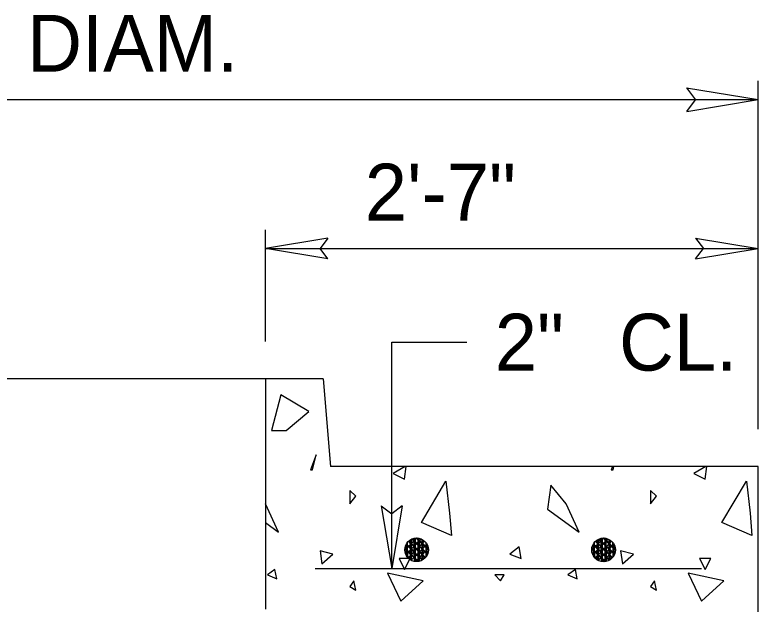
# Model space of a CAD drawing. Extents: x 1.8 to 9.1, y -6 to 4.
# Drawn here: x 5.989 to 6.774, y 1.281 to 1.904 of the extents above; entities that cross this region are included whole.
import ezdxf

# ---------------------------------------------------------------- set-up
doc = ezdxf.new("R2010")
doc.units = 0
for name, color, linetype in [('DETL-DIMS', 7, 'Continuous'), ('DETL-LINE', 7, 'Continuous'), ('DETL-NOTE', 7, 'Continuous'), ('DETL-PATT', 7, 'Continuous')]:
    doc.layers.add(name, color=color, linetype=linetype)

msp = doc.modelspace()

# ---------------------------------------------------------------- linework, layer by layer
at = {"layer": 'DETL-DIMS'}
for p, q in [((6.77389, 1.4659), (6.77389, 1.83373)), ((6.69839, 1.82649), (6.77389, 1.81407)), ((6.69839, 1.82649), (6.70786, 1.81395)), ((5.11586, 1.81407), (6.77389, 1.81407)), ((6.69846, 1.80134), (6.77389, 1.81407)), ((6.69846, 1.80134), (6.70786, 1.81395)), ((6.25356, 1.55859), (6.25356, 1.6765)), ((6.3196, 1.66786), (6.25356, 1.65685)), ((6.3196, 1.66786), (6.31134, 1.65685)), ((6.70786, 1.66786), (6.77389, 1.65685)), ((6.70786, 1.66786), (6.71611, 1.65685)), ((6.3196, 1.64584), (6.25356, 1.65685)), ((6.25356, 1.65685), (6.77389, 1.65685)), ((6.3196, 1.64584), (6.31134, 1.65685)), ((6.70786, 1.64584), (6.77389, 1.65685)), ((6.70786, 1.64584), (6.71611, 1.65685)), ((6.38689, 1.31894), (6.38689, 1.55788)), ((6.38689, 1.55788), (6.46629, 1.55788)), ((6.37588, 1.38497), (6.38689, 1.31894)), ((6.37588, 1.38497), (6.38689, 1.37672)), ((6.39789, 1.38497), (6.38689, 1.31894)), ((6.39789, 1.38497), (6.38689, 1.37672))]:
    msp.add_line(p, q, dxfattribs=at)
at = {"layer": 'DETL-LINE'}
for p, q in [((6.31468, 1.51928), (5.26346, 1.51928)), ((6.25356, 1.51928), (6.25356, 1.27578)), ((6.31468, 1.51928), (6.32239, 1.4266)), ((6.77389, 1.4266), (6.32239, 1.4266)), ((6.77389, 1.189), (6.77389, 1.4266)), ((6.41169, 1.3494), (6.40238, 1.34001)), ((6.41169, 1.34358), (6.40241, 1.33415)), ((6.40379, 1.33061), (6.40371, 1.34386)), ((6.41311, 1.33336), (6.40371, 1.34268)), ((6.41342, 1.3338), (6.40403, 1.34311)), ((6.4146, 1.34649), (6.40528, 1.3371)), ((6.4067, 1.33478), (6.40662, 1.34803)), ((6.41601, 1.33631), (6.40662, 1.34559)), ((6.40674, 1.33065), (6.40666, 1.3439)), ((6.41633, 1.33675), (6.4069, 1.34606)), ((6.40788, 1.33478), (6.4078, 1.34803)), ((6.40792, 1.33065), (6.40784, 1.3439)), ((6.41751, 1.34944), (6.40819, 1.34005)), ((6.41755, 1.34362), (6.40823, 1.33419)), ((6.41892, 1.33926), (6.40953, 1.34854)), ((6.41896, 1.3334), (6.40957, 1.34272)), ((6.41924, 1.33969), (6.4098, 1.34901)), ((6.41928, 1.33384), (6.4098, 1.34315)), ((6.41083, 1.33478), (6.41075, 1.34803)), ((6.41087, 1.33065), (6.41079, 1.3439)), ((6.42042, 1.34653), (6.41114, 1.33714)), ((6.41201, 1.33482), (6.41193, 1.34803)), ((6.41204, 1.33069), (6.41197, 1.3439)), ((6.42187, 1.33635), (6.41244, 1.34563)), ((6.42219, 1.33678), (6.41271, 1.3461)), ((6.42336, 1.34362), (6.41409, 1.33423)), ((6.41495, 1.33482), (6.41487, 1.34807)), ((6.41499, 1.33069), (6.41491, 1.34394)), ((6.42478, 1.3393), (6.41535, 1.34858)), ((6.42505, 1.33973), (6.41562, 1.34901)), ((6.41613, 1.33482), (6.41605, 1.34807)), ((6.41617, 1.33069), (6.41609, 1.34394)), ((6.41908, 1.33486), (6.419, 1.34807)), ((6.41912, 1.33073), (6.41904, 1.34398)), ((6.42026, 1.33486), (6.42018, 1.3481)), ((6.4203, 1.33073), (6.42022, 1.34398)), ((6.60916, 1.34932), (6.59985, 1.33993)), ((6.60916, 1.34351), (6.59989, 1.33407)), ((6.60126, 1.33053), (6.60118, 1.34378)), ((6.61058, 1.33329), (6.60118, 1.3426)), ((6.61089, 1.33372), (6.6015, 1.34303)), ((6.61207, 1.34641), (6.60276, 1.33702)), ((6.60417, 1.3347), (6.60409, 1.34795)), ((6.61349, 1.33623), (6.60409, 1.34551)), ((6.60421, 1.33057), (6.60413, 1.34382)), ((6.6138, 1.33667), (6.60437, 1.34598)), ((6.60535, 1.3347), (6.60527, 1.34795)), ((6.60539, 1.33057), (6.60531, 1.34382)), ((6.61498, 1.34936), (6.60566, 1.33997)), ((6.61502, 1.34354), (6.6057, 1.33411)), ((6.61639, 1.33918), (6.607, 1.34846)), ((6.61643, 1.33333), (6.60704, 1.34264)), ((6.61671, 1.33961), (6.60728, 1.34893)), ((6.61675, 1.33376), (6.60728, 1.34307)), ((6.6083, 1.3347), (6.60822, 1.34795)), ((6.60834, 1.33057), (6.60826, 1.34382)), ((6.61789, 1.34645), (6.60861, 1.33706)), ((6.60948, 1.33474), (6.6094, 1.34795)), ((6.60952, 1.33061), (6.60944, 1.34382)), ((6.61934, 1.33627), (6.60991, 1.34555)), ((6.61966, 1.33671), (6.61018, 1.34602)), ((6.62084, 1.34354), (6.61156, 1.33415)), ((6.61242, 1.33474), (6.61235, 1.34799)), ((6.61246, 1.33061), (6.61239, 1.34386)), ((6.62225, 1.33922), (6.61282, 1.3485)), ((6.62253, 1.33965), (6.61309, 1.34893)), ((6.6136, 1.33474), (6.61353, 1.34799)), ((6.61364, 1.33061), (6.61356, 1.34386)), ((6.61655, 1.33478), (6.61647, 1.34799)), ((6.61659, 1.33065), (6.61651, 1.3439)), ((6.61773, 1.33478), (6.61765, 1.34803)), ((6.61777, 1.33065), (6.61769, 1.3439)), ((6.41024, 1.33046), (6.4008, 1.33977)), ((6.41051, 1.33089), (6.40112, 1.34016)), ((6.41315, 1.32755), (6.40375, 1.33686)), ((6.41346, 1.32798), (6.40407, 1.3373)), ((6.41464, 1.34071), (6.40532, 1.33124)), ((6.41605, 1.3305), (6.40666, 1.33977)), ((6.41637, 1.33093), (6.40694, 1.3402)), ((6.41759, 1.33781), (6.40827, 1.32833)), ((6.419, 1.32759), (6.40957, 1.3369)), ((6.41932, 1.32802), (6.40984, 1.33733)), ((6.4109, 1.32653), (6.41079, 1.33977)), ((6.42046, 1.34071), (6.41118, 1.33128)), ((6.41204, 1.32656), (6.41197, 1.33977)), ((6.42191, 1.33053), (6.41248, 1.33981)), ((6.42222, 1.33093), (6.41275, 1.34024)), ((6.4234, 1.33785), (6.41409, 1.32837)), ((6.41499, 1.32656), (6.41491, 1.33981)), ((6.41617, 1.32656), (6.41609, 1.33981)), ((6.60771, 1.33038), (6.59827, 1.33969)), ((6.60798, 1.33081), (6.59859, 1.34009)), ((6.61062, 1.32747), (6.60122, 1.33678)), ((6.61093, 1.3279), (6.60154, 1.33722)), ((6.61211, 1.34064), (6.6028, 1.33116)), ((6.61353, 1.33042), (6.60413, 1.33969)), ((6.61384, 1.33085), (6.60441, 1.34013)), ((6.61506, 1.33773), (6.60574, 1.32826)), ((6.61647, 1.32751), (6.60704, 1.33682)), ((6.61679, 1.32794), (6.60732, 1.33726)), ((6.60838, 1.32645), (6.60826, 1.33969)), ((6.61793, 1.34064), (6.60865, 1.3312)), ((6.60952, 1.32649), (6.60944, 1.33969)), ((6.61938, 1.33046), (6.60995, 1.33973)), ((6.6197, 1.33085), (6.61022, 1.34016)), ((6.62088, 1.33777), (6.61156, 1.32829)), ((6.61246, 1.32649), (6.61239, 1.33973)), ((6.61364, 1.32649), (6.61356, 1.33973)), ((6.30592, 1.31894), (6.71399, 1.31894))]:
    msp.add_line(p, q, dxfattribs=at)
for points in [[(6.41326, 1.35105), (6.40524, 1.34296)], [(6.41326, 1.35105), (6.40815, 1.3459)], [(6.41629, 1.3426), (6.40863, 1.35019)], [(6.41334, 1.34551), (6.40863, 1.35019)], [(6.41039, 1.34838), (6.40863, 1.35019)], [(6.41083, 1.33891), (6.41075, 1.35082)], [(6.41079, 1.34303), (6.41075, 1.35082)], [(6.41075, 1.34716), (6.41075, 1.35082)], [(6.41197, 1.33895), (6.41189, 1.35101)], [(6.41197, 1.34307), (6.41189, 1.35101)], [(6.41193, 1.3472), (6.41189, 1.35101)], [(6.42183, 1.34217), (6.41287, 1.35105)], [(6.41888, 1.34508), (6.41287, 1.35105)], [(6.41594, 1.34799), (6.41287, 1.35105)], [(6.41299, 1.3509), (6.41287, 1.35105)], [(6.42215, 1.34264), (6.41358, 1.35105)], [(6.4192, 1.34555), (6.41358, 1.35105)], [(6.41625, 1.34842), (6.41358, 1.35105)], [(6.41495, 1.33895), (6.41487, 1.3509)], [(6.41491, 1.34307), (6.41487, 1.3509)], [(6.41487, 1.3472), (6.41487, 1.3509)], [(6.41609, 1.33895), (6.41601, 1.3507)], [(6.41609, 1.34307), (6.41601, 1.3507)], [(6.41605, 1.3472), (6.41601, 1.3507)], [(6.61073, 1.35097), (6.60272, 1.34288)], [(6.61073, 1.35097), (6.60563, 1.34582)], [(6.6083, 1.33883), (6.60822, 1.35074)], [(6.60826, 1.34296), (6.60822, 1.35074)], [(6.60822, 1.34708), (6.60822, 1.35074)], [(6.60944, 1.33887), (6.60936, 1.35093)], [(6.60944, 1.34299), (6.60936, 1.35093)], [(6.6094, 1.34712), (6.60936, 1.35093)], [(6.6193, 1.34209), (6.61034, 1.35097)], [(6.61636, 1.345), (6.61034, 1.35097)], [(6.61341, 1.34791), (6.61034, 1.35097)], [(6.61046, 1.35082), (6.61034, 1.35097)], [(6.61962, 1.34256), (6.61105, 1.35097)], [(6.61667, 1.34547), (6.61105, 1.35097)], [(6.61372, 1.34834), (6.61105, 1.35097)], [(6.61242, 1.33887), (6.61235, 1.35082)], [(6.61239, 1.34299), (6.61235, 1.35082)], [(6.61235, 1.34712), (6.61235, 1.35082)], [(6.61356, 1.33887), (6.61349, 1.35062)], [(6.61356, 1.34299), (6.61349, 1.35062)], [(6.61353, 1.34712), (6.61349, 1.35062)], [(6.40878, 1.34649), (6.40072, 1.33836)], [(6.40587, 1.34354), (6.40072, 1.33836)], [(6.4102, 1.33627), (6.4021, 1.34425)], [(6.40725, 1.33918), (6.4021, 1.34425)], [(6.40434, 1.34209), (6.4021, 1.34425)], [(6.41047, 1.33671), (6.40234, 1.34476)], [(6.40752, 1.33961), (6.40234, 1.34476)], [(6.40462, 1.34252), (6.40234, 1.34476)], [(6.40257, 1.33474), (6.40253, 1.34504)], [(6.40257, 1.33887), (6.40253, 1.34504)], [(6.40253, 1.34299), (6.40253, 1.34504)], [(6.40261, 1.33203), (6.40253, 1.34386)], [(6.40375, 1.33474), (6.40367, 1.34665)], [(6.40371, 1.33887), (6.40367, 1.34665)], [(6.40371, 1.34299), (6.40367, 1.34665)], [(6.41307, 1.33922), (6.40458, 1.34763)], [(6.41016, 1.34213), (6.40458, 1.34763)], [(6.40725, 1.34504), (6.40458, 1.34763)], [(6.41338, 1.33965), (6.40497, 1.34795)], [(6.41043, 1.34256), (6.40497, 1.34795)], [(6.40749, 1.34547), (6.40497, 1.34795)], [(6.4067, 1.33891), (6.40662, 1.34917)], [(6.40666, 1.34303), (6.40662, 1.34917)], [(6.40662, 1.34716), (6.40662, 1.34917)], [(6.40784, 1.33891), (6.4078, 1.34983)], [(6.40784, 1.34303), (6.4078, 1.34983)], [(6.4078, 1.34716), (6.4078, 1.34983)], [(6.41598, 1.34217), (6.40811, 1.34995)], [(6.41303, 1.34504), (6.40811, 1.34995)], [(6.41012, 1.34795), (6.40811, 1.34995)], [(6.4181, 1.35003), (6.4111, 1.34299)], [(6.42164, 1.34775), (6.41405, 1.34009)], [(6.42462, 1.3336), (6.41539, 1.34276)], [(6.42482, 1.33415), (6.41566, 1.34319)], [(6.42419, 1.34449), (6.41696, 1.33718)], [(6.42564, 1.33844), (6.41826, 1.34567)], [(6.42564, 1.33914), (6.41857, 1.34614)], [(6.41908, 1.33899), (6.419, 1.3496)], [(6.41904, 1.34311), (6.419, 1.3496)], [(6.419, 1.34724), (6.419, 1.3496)], [(6.42022, 1.33899), (6.42018, 1.34893)], [(6.42022, 1.34311), (6.42018, 1.34893)], [(6.42018, 1.34724), (6.42018, 1.34893)], [(6.42564, 1.33844), (6.4212, 1.3428)], [(6.42564, 1.33914), (6.42152, 1.34323)], [(6.42321, 1.33486), (6.42313, 1.3461)], [(6.42321, 1.33899), (6.42313, 1.3461)], [(6.42317, 1.34311), (6.42313, 1.3461)], [(6.42325, 1.33124), (6.42317, 1.34398)], [(6.42439, 1.3349), (6.42431, 1.34421)], [(6.42435, 1.33899), (6.42431, 1.34421)], [(6.42435, 1.34311), (6.42431, 1.34421)], [(6.42439, 1.33309), (6.42431, 1.34398)], [(6.60625, 1.34641), (6.5982, 1.33828)], [(6.60335, 1.34347), (6.5982, 1.33828)], [(6.60767, 1.33619), (6.59957, 1.34417)], [(6.60472, 1.3391), (6.59957, 1.34417)], [(6.60181, 1.34201), (6.59957, 1.34417)], [(6.60794, 1.33663), (6.59981, 1.34468)], [(6.605, 1.33954), (6.59981, 1.34468)], [(6.60209, 1.34244), (6.59981, 1.34468)], [(6.60004, 1.33466), (6.6, 1.34496)], [(6.60004, 1.33879), (6.6, 1.34496)], [(6.6, 1.34292), (6.6, 1.34496)], [(6.60008, 1.33195), (6.6, 1.34378)], [(6.60122, 1.33466), (6.60114, 1.34657)], [(6.60118, 1.33879), (6.60114, 1.34657)], [(6.60118, 1.34292), (6.60114, 1.34657)], [(6.61054, 1.33914), (6.60205, 1.34755)], [(6.60763, 1.34205), (6.60205, 1.34755)], [(6.60472, 1.34496), (6.60205, 1.34755)], [(6.61085, 1.33958), (6.60244, 1.34787)], [(6.6079, 1.34248), (6.60244, 1.34787)], [(6.60496, 1.34539), (6.60244, 1.34787)], [(6.60417, 1.33883), (6.60409, 1.34909)], [(6.60413, 1.34296), (6.60409, 1.34909)], [(6.60409, 1.34708), (6.60409, 1.34909)], [(6.60531, 1.33883), (6.60527, 1.34976)], [(6.60531, 1.34296), (6.60527, 1.34976)], [(6.60527, 1.34708), (6.60527, 1.34976)], [(6.61345, 1.34209), (6.60559, 1.34987)], [(6.6105, 1.34496), (6.60559, 1.34987)], [(6.60759, 1.34787), (6.60559, 1.34987)], [(6.61376, 1.34252), (6.6061, 1.35011)], [(6.61081, 1.34543), (6.6061, 1.35011)], [(6.60787, 1.3483), (6.6061, 1.35011)], [(6.61557, 1.34995), (6.60857, 1.34292)], [(6.61911, 1.34767), (6.61152, 1.34001)], [(6.62209, 1.33352), (6.61286, 1.34268)], [(6.62229, 1.33407), (6.61313, 1.34311)], [(6.62166, 1.34441), (6.61443, 1.3371)], [(6.62312, 1.33836), (6.61573, 1.34559)], [(6.62312, 1.33906), (6.61604, 1.34606)], [(6.61655, 1.33891), (6.61647, 1.34952)], [(6.61651, 1.34303), (6.61647, 1.34952)], [(6.61647, 1.34716), (6.61647, 1.34952)], [(6.61769, 1.33891), (6.61765, 1.34885)], [(6.61769, 1.34303), (6.61765, 1.34885)], [(6.61765, 1.34716), (6.61765, 1.34885)], [(6.62312, 1.33836), (6.61867, 1.34272)], [(6.62312, 1.33906), (6.61899, 1.34315)], [(6.62068, 1.33478), (6.6206, 1.34602)], [(6.62068, 1.33891), (6.6206, 1.34602)], [(6.62064, 1.34303), (6.6206, 1.34602)], [(6.62072, 1.33116), (6.62064, 1.3439)], [(6.62186, 1.33482), (6.62178, 1.34413)], [(6.62182, 1.33891), (6.62178, 1.34413)], [(6.62182, 1.34303), (6.62178, 1.34413)], [(6.62186, 1.33301), (6.62178, 1.3439)], [(6.40297, 1.34064), (6.40072, 1.33836)], [(6.40729, 1.33333), (6.4008, 1.33977)], [(6.40438, 1.33623), (6.4008, 1.33977)], [(6.40143, 1.33914), (6.4008, 1.33977)], [(6.40756, 1.3338), (6.40088, 1.34044)], [(6.40462, 1.33667), (6.40088, 1.34044)], [(6.40175, 1.33958), (6.40088, 1.34044)], [(6.40882, 1.34068), (6.40179, 1.33352)], [(6.40591, 1.33773), (6.40179, 1.33352)], [(6.403, 1.33478), (6.40179, 1.33352)], [(6.40261, 1.33203), (6.40257, 1.33973)], [(6.40261, 1.33203), (6.40257, 1.33561)], [(6.40379, 1.33042), (6.40371, 1.33973)], [(6.40379, 1.33042), (6.40375, 1.33561)], [(6.41173, 1.33777), (6.40414, 1.33006)], [(6.40882, 1.33482), (6.40414, 1.33006)], [(6.40674, 1.32794), (6.40666, 1.33977)], [(6.40674, 1.32794), (6.4067, 1.33564)], [(6.41468, 1.33486), (6.40745, 1.32751)], [(6.40792, 1.32727), (6.40784, 1.33977)], [(6.40792, 1.32727), (6.40788, 1.33564)], [(6.4109, 1.32633), (6.41083, 1.33564)], [(6.4205, 1.3349), (6.41193, 1.32621)], [(6.41204, 1.32617), (6.41201, 1.33564)], [(6.41503, 1.32625), (6.41495, 1.33568)], [(6.42234, 1.3301), (6.41543, 1.3369)], [(6.42266, 1.3305), (6.4157, 1.33737)], [(6.41617, 1.32649), (6.41613, 1.33568)], [(6.42557, 1.34001), (6.417, 1.33132)], [(6.42462, 1.3336), (6.41829, 1.33985)], [(6.42482, 1.33415), (6.41861, 1.34028)], [(6.41912, 1.32763), (6.41904, 1.33985)], [(6.41912, 1.32763), (6.41908, 1.33572)], [(6.42557, 1.34001), (6.41991, 1.33427)], [(6.4203, 1.32837), (6.42022, 1.33985)], [(6.4203, 1.32837), (6.42026, 1.33572)], [(6.42325, 1.33124), (6.42317, 1.33985)], [(6.42325, 1.33124), (6.42321, 1.33572)], [(6.42439, 1.33309), (6.42435, 1.33985)], [(6.42439, 1.33309), (6.42439, 1.33572)], [(6.60044, 1.34056), (6.5982, 1.33828)], [(6.60476, 1.33325), (6.59827, 1.33969)], [(6.60185, 1.33616), (6.59827, 1.33969)], [(6.5989, 1.33906), (6.59827, 1.33969)], [(6.60504, 1.33372), (6.59835, 1.34036)], [(6.60209, 1.33659), (6.59835, 1.34036)], [(6.59922, 1.3395), (6.59835, 1.34036)], [(6.60629, 1.3406), (6.59926, 1.33344)], [(6.60338, 1.33765), (6.59926, 1.33344)], [(6.60048, 1.3347), (6.59926, 1.33344)], [(6.60008, 1.33195), (6.60004, 1.33965)], [(6.60008, 1.33195), (6.60004, 1.33553)], [(6.60126, 1.33034), (6.60118, 1.33965)], [(6.60126, 1.33034), (6.60122, 1.33553)], [(6.6092, 1.33769), (6.60162, 1.32998)], [(6.60629, 1.33474), (6.60162, 1.32998)], [(6.60421, 1.32786), (6.60413, 1.33969)], [(6.60421, 1.32786), (6.60417, 1.33557)], [(6.61215, 1.33478), (6.60492, 1.32743)], [(6.60539, 1.32719), (6.60531, 1.33969)], [(6.60539, 1.32719), (6.60535, 1.33557)], [(6.60838, 1.32625), (6.6083, 1.33557)], [(6.61797, 1.33482), (6.6094, 1.32613)], [(6.60952, 1.32609), (6.60948, 1.33557)], [(6.6125, 1.32617), (6.61242, 1.33561)], [(6.61981, 1.33002), (6.6129, 1.33682)], [(6.62013, 1.33042), (6.61317, 1.3373)], [(6.61364, 1.32641), (6.6136, 1.33561)], [(6.62304, 1.33993), (6.61447, 1.33124)], [(6.62209, 1.33352), (6.61577, 1.33977)], [(6.62229, 1.33407), (6.61608, 1.3402)], [(6.61659, 1.32755), (6.61651, 1.33977)], [(6.61659, 1.32755), (6.61655, 1.33564)], [(6.62304, 1.33993), (6.61738, 1.33419)], [(6.61777, 1.32829), (6.61769, 1.33977)], [(6.61777, 1.32829), (6.61773, 1.33564)], [(6.62072, 1.33116), (6.62064, 1.33977)], [(6.62072, 1.33116), (6.62068, 1.33564)], [(6.62186, 1.33301), (6.62182, 1.33977)], [(6.62186, 1.33301), (6.62186, 1.33564)], [(6.40859, 1.327), (6.40167, 1.33384)], [(6.4076, 1.32794), (6.40167, 1.33384)], [(6.40466, 1.33085), (6.40167, 1.33384)], [(6.40175, 1.33376), (6.40167, 1.33384)], [(6.40721, 1.32763), (6.40234, 1.33246)], [(6.40721, 1.32763), (6.40234, 1.33246)], [(6.40438, 1.33042), (6.40234, 1.33246)], [(6.40721, 1.32763), (6.40379, 1.33101)], [(6.40859, 1.327), (6.40407, 1.33144)], [(6.40595, 1.33187), (6.40414, 1.33006)], [(6.41452, 1.32617), (6.4067, 1.33395)], [(6.40721, 1.32763), (6.4067, 1.3281)], [(6.41515, 1.32629), (6.40697, 1.33439)], [(6.40859, 1.327), (6.40701, 1.32853)], [(6.41177, 1.33191), (6.40745, 1.32751)], [(6.40886, 1.32896), (6.40745, 1.32751)], [(6.41452, 1.32617), (6.40961, 1.33105)], [(6.41515, 1.32629), (6.40988, 1.33148)], [(6.41763, 1.33195), (6.41193, 1.32621)], [(6.41472, 1.329), (6.41193, 1.32621)], [(6.41904, 1.32755), (6.41252, 1.33399)], [(6.41947, 1.32782), (6.41279, 1.33443)], [(6.42427, 1.33278), (6.41912, 1.32759)], [(6.42344, 1.33199), (6.41912, 1.32759)], [(6.42053, 1.32904), (6.41912, 1.32759)], [(6.42427, 1.33278), (6.41995, 1.32841)], [(6.42427, 1.33278), (6.42285, 1.33136)], [(6.60606, 1.32692), (6.59914, 1.33376)], [(6.60507, 1.32786), (6.59914, 1.33376)], [(6.60213, 1.33077), (6.59914, 1.33376)], [(6.59922, 1.33368), (6.59914, 1.33376)], [(6.60468, 1.32755), (6.59981, 1.33238)], [(6.60468, 1.32755), (6.59981, 1.33238)], [(6.60185, 1.33034), (6.59981, 1.33238)], [(6.60468, 1.32755), (6.60126, 1.33093)], [(6.60606, 1.32692), (6.60154, 1.33136)], [(6.60342, 1.33179), (6.60162, 1.32998)], [(6.61199, 1.32609), (6.60417, 1.33388)], [(6.60468, 1.32755), (6.60417, 1.32802)], [(6.61262, 1.32621), (6.60445, 1.33431)], [(6.60606, 1.32692), (6.60449, 1.32845)], [(6.60924, 1.33183), (6.60492, 1.32743)], [(6.60633, 1.32888), (6.60492, 1.32743)], [(6.61199, 1.32609), (6.60708, 1.33097)], [(6.61262, 1.32621), (6.60735, 1.3314)], [(6.6151, 1.33187), (6.6094, 1.32613)], [(6.61219, 1.32892), (6.6094, 1.32613)], [(6.61651, 1.32747), (6.60999, 1.33392)], [(6.61695, 1.32774), (6.61026, 1.33435)], [(6.62174, 1.3327), (6.61659, 1.32751)], [(6.62091, 1.33191), (6.61659, 1.32751)], [(6.61801, 1.32896), (6.61659, 1.32751)], [(6.62174, 1.3327), (6.61742, 1.32833)], [(6.62174, 1.3327), (6.62033, 1.33128)]]:
    msp.add_lwpolyline(points, dxfattribs=at)
for centre in [(6.41319, 1.33859), (6.61066, 1.33852)]:
    msp.add_circle(centre, 0.01249, dxfattribs=at)
at = {"layer": 'DETL-PATT'}
for points in [[(6.27538, 1.46449), (6.29943, 1.48477), (6.26972, 1.50222), (6.25981, 1.46449)], [(6.30132, 1.42298), (6.30321, 1.42298), (6.30698, 1.43902)], [(6.44801, 1.37723), (6.4499, 1.35365), (6.41829, 1.36732), (6.44424, 1.41119)], [(6.55508, 1.40694), (6.5513, 1.38147), (6.58479, 1.35742), (6.57111, 1.38713)], [(6.76544, 1.37723), (6.76733, 1.35365), (6.73573, 1.36732), (6.76167, 1.41119)], [(6.34283, 1.40128), (6.34283, 1.38713), (6.34896, 1.39515)], [(6.66026, 1.40128), (6.66026, 1.38713), (6.66639, 1.39515)], [(6.31123, 1.33761), (6.31311, 1.32393), (6.3249, 1.33384)], [(6.52159, 1.34185), (6.51168, 1.33384), (6.52348, 1.32959)], [(6.62866, 1.33761), (6.63054, 1.32393), (6.64234, 1.33384)], [(6.39471, 1.32959), (6.40037, 1.3178), (6.4065, 1.32959)], [(6.71214, 1.32959), (6.7178, 1.3178), (6.72393, 1.32959)], [(6.25557, 1.31214), (6.26547, 1.30789), (6.26359, 1.3178)], [(6.38245, 1.31403), (6.3966, 1.28431), (6.42018, 1.30601)], [(6.49565, 1.31214), (6.50178, 1.30601), (6.50555, 1.31214)], [(6.573, 1.31214), (6.58291, 1.30789), (6.58102, 1.3178)], [(6.69988, 1.31403), (6.71403, 1.28431), (6.73761, 1.30601)], [(6.34283, 1.29988), (6.34896, 1.2961), (6.34707, 1.30601)], [(6.66026, 1.29988), (6.66639, 1.2961), (6.6645, 1.30601)]]:
    msp.add_lwpolyline(points, close=True, dxfattribs=at)
for points in [[(6.4012, 1.4266), (6.38858, 1.41921), (6.40037, 1.41308), (6.40218, 1.4266)], [(6.62005, 1.4266), (6.61875, 1.42298), (6.62064, 1.42298), (6.6215, 1.4266)], [(6.71863, 1.4266), (6.70601, 1.41921), (6.7178, 1.41308), (6.71961, 1.4266)], [(6.25356, 1.36732), (6.26736, 1.35742), (6.25368, 1.38713), (6.25356, 1.38725)]]:
    msp.add_lwpolyline(points, dxfattribs=at)

# ---------------------------------------------------------------- texts
at = {"layer": 'DETL-NOTE'}
for s, p in [('DIAM.', (6.00193, 1.84355)), ('2\'-7"', (6.35847, 1.68633)), ('2"', (6.49577, 1.52789)), ('CL.', (6.62701, 1.52789))]:
    msp.add_text(s, height=0.05998, dxfattribs=at).set_placement(p)

doc.saveas('drawing.dxf')
